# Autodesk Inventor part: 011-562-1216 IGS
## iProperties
Created: 2010-02
Part Number: 011-562-1216 IGS
Document SubType Name: Modeling
Designer: Alex_Cyril
Author: Alex_Cyril
Norme de conversion: IGES 5.3
Nom du fichier: \\Bisondraw\drawings\SOLIDWORKS CUSTOMER ASSY\011-562-1216\011-562-1216.IGS
Préprocesseur: SolidWorks 2009
Postprocesseur: Build: 391, Release: 11 SP3 - Date: Tue 06/05/2007
Unités envoyées: MM
Incertitude: 1e-08
